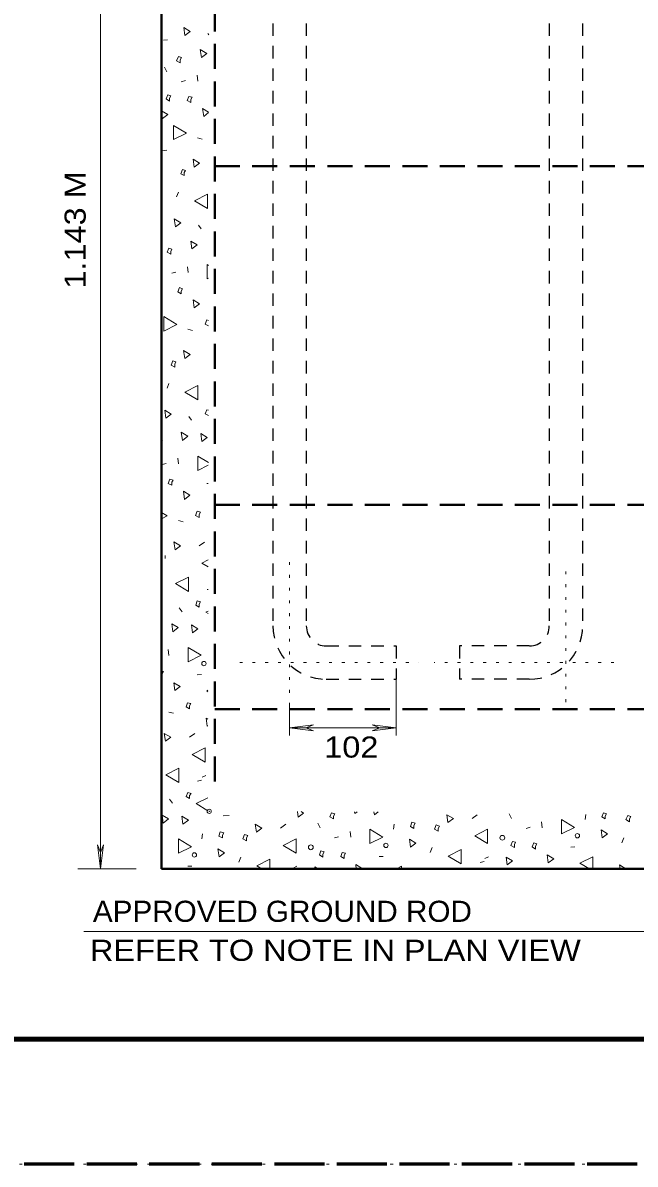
# Model space of a CAD drawing. Extents: x 312583 to 312854, y 144419 to 144597.
# Drawn here: x 312692.4 to 312714.43, y 144418.58 to 144459.67 of the extents above; entities that cross this region are included whole.
import ezdxf

# ---------------------------------------------------------------- set-up
doc = ezdxf.new("R2010")
doc.units = 0
doc.header["$LTSCALE"] = 0.3
doc.header["$PDMODE"] = 32
doc.header["$PDSIZE"] = 0.15
for name, pattern in [('DOTTED', [1.5, 0.3, -1.2]), ('LONG_DASHED', [7.5, 6, -1.5]), ('MEDIUM_DASHED', [4.5, 3, -1.5]), ('SHORT_DASHED', [2.7, 1.5, -1.2])]:
    doc.linetypes.add(name, pattern=pattern)
doc.layers.add('1', color=7, linetype='Continuous', lineweight=13)
doc.layers.add('63', color=7, linetype='DOTTED', lineweight=13)

msp = doc.modelspace()

# ---------------------------------------------------------------- linework, layer by layer
at = {"layer": '1'}
for p, q in [((312695.1883, 144429.2169), (312695.1883, 144472.3419)), ((312699.0599, 144459.2855), (312699.0906, 144459.2395)), ((312697.4576, 144459.0479), (312697.6033, 144459.0632)), ((312697.4959, 144458.0742), (312697.5803, 144457.9055)), ((312698.1016, 144457.5452), (312698.2473, 144457.5912)), ((312698.6689, 144457.7829), (312698.6919, 144457.5682)), ((312697.3886, 144456.4949), (312697.4269, 144456.2265)), ((312698.9066, 144456.3032), (312699.0829, 144456.4412)), ((312698.6843, 144455.5289), (312698.8529, 144455.4905)), ((312697.3886, 144455.0689), (312697.5803, 144455.0842)), ((312698.0019, 144453.5815), (312697.9253, 144453.4129)), ((312698.7149, 144452.3932), (312698.8146, 144452.2552)), ((312697.7566, 144450.6605), (312697.9023, 144450.6989)), ((312698.3239, 144450.8905), (312698.3469, 144450.6835)), ((312699.0829, 144450.9365), (312699.0293, 144450.9672)), ((312698.3393, 144448.6442), (312698.5079, 144448.5982)), ((312697.6569, 144446.6892), (312697.5879, 144446.5205)), ((312698.3699, 144445.5009), (312698.4696, 144445.3629)), ((312697.9789, 144443.9982), (312698.0019, 144443.7912)), ((312699.0753, 144443.8449), (312698.6919, 144444.0749)), ((312697.4116, 144443.7682), (312697.5573, 144443.8065)), ((312699.0216, 144443.0935), (312699.0676, 144443.0935)), ((312697.9943, 144441.7519), (312698.1629, 144441.7059)), ((312698.9296, 144440.9775), (312698.7456, 144440.8472)), ((312697.5189, 144440.3872), (312697.5189, 144440.4945)), ((312699.0293, 144439.2679), (312699.0676, 144439.2755)), ((312698.0249, 144438.6162), (312698.1323, 144438.4705)), ((312697.6339, 144437.1135), (312697.6569, 144436.8989)), ((312698.6766, 144436.2012), (312698.8223, 144436.2089)), ((312705.8296, 144436.0402), (312705.8296, 144434.0162)), ((312701.9963, 144435.0972), (312701.9963, 144434.0162)), ((312697.6493, 144434.8595), (312697.8179, 144434.8212)), ((312699.0369, 144434.3535), (312699.0599, 144434.3689)), ((312701.9963, 144434.2922), (312702.8626, 144434.3995)), ((312701.9963, 144434.2922), (312705.8296, 144434.2922)), ((312701.9963, 144434.2922), (312702.8626, 144434.1849)), ((312702.8626, 144434.3995), (312702.5866, 144434.2922)), ((312702.8626, 144434.1849), (312702.5866, 144434.2922)), ((312704.9633, 144434.3995), (312705.2393, 144434.2922)), ((312705.8296, 144434.2922), (312704.9633, 144434.3995)), ((312704.9633, 144434.1849), (312705.2393, 144434.2922)), ((312705.8296, 144434.2922), (312704.9633, 144434.1849)), ((312698.5846, 144434.0852), (312698.4006, 144433.9549)), ((312698.8529, 144432.5135), (312698.9833, 144432.5825)), ((312698.6843, 144432.3755), (312698.8299, 144432.4062)), ((312697.6799, 144431.7239), (312697.7873, 144431.5782)), ((312699.0983, 144431.2869), (312699.1059, 144431.2869)), ((312702.2799, 144431.2792), (312702.3106, 144431.0799)), ((312704.3346, 144431.2715), (312704.3423, 144431.2102)), ((312704.3423, 144431.2102), (312704.4266, 144431.2715)), ((312705.0323, 144431.2715), (312705.0476, 144431.1642)), ((312705.0476, 144431.1642), (312705.1856, 144431.2715)), ((312699.6043, 144431.1259), (312699.8189, 144431.1335)), ((312703.0083, 144430.8575), (312703.1003, 144430.6889)), ((312708.7506, 144431.1565), (312708.5666, 144431.0262)), ((312709.9006, 144431.2025), (312709.9849, 144431.0339)), ((312711.0659, 144430.9112), (312711.0889, 144430.6965)), ((312712.6299, 144430.9879), (312712.6529, 144431.1719)), ((312698.8453, 144430.2979), (312698.8683, 144430.4819)), ((312701.8583, 144430.8192), (312701.6743, 144430.6812)), ((312704.1813, 144430.5662), (312704.2043, 144430.3515)), ((312705.7376, 144430.6429), (312705.7606, 144430.8269)), ((312710.5063, 144430.6735), (312710.6519, 144430.7195)), ((312695.0809, 144430.0832), (312695.1883, 144429.8072)), ((312695.1883, 144429.2169), (312695.0809, 144430.0832)), ((312695.2956, 144430.0832), (312695.1883, 144429.8072)), ((312695.1883, 144429.2169), (312695.2956, 144430.0832)), ((312703.6139, 144430.3285), (312703.7596, 144430.3745)), ((312714.0253, 144430.3285), (312713.9486, 144430.1522)), ((312700.2483, 144429.6385), (312700.1716, 144429.4622)), ((312705.2239, 144429.6615), (312705.3696, 144429.6615)), ((312707.1329, 144429.9835), (312707.0563, 144429.8072)), ((312709.0189, 144429.5849), (312709.1493, 144429.6539)), ((312712.1163, 144429.9989), (312712.2619, 144430.0065)), ((312696.4763, 144429.2169), (312694.3756, 144429.2169)), ((312698.3316, 144429.3165), (312698.4773, 144429.3165)), ((312702.1266, 144429.2399), (312702.2569, 144429.3089)), ((312708.8503, 144429.4469), (312708.9959, 144429.4775)), ((312694.5903, 144426.9629), (312718.4949, 144426.9629))]:
    msp.add_line(p, q, dxfattribs=at)
at = {"layer": '1', "linetype": 'SHORT_DASHED', "lineweight": 25}
for p, q in [((312701.3983, 144470.1799), (312701.3983, 144437.9569)), ((312702.5943, 144470.1799), (312702.5943, 144437.9569)), ((312711.3419, 144470.1799), (312711.3419, 144437.9569)), ((312712.5379, 144470.1799), (312712.5379, 144437.9569)), ((312703.3149, 144437.2439), (312705.8296, 144437.2439)), ((312705.8296, 144437.2439), (312705.8296, 144436.0402)), ((312708.1066, 144437.2439), (312708.1066, 144436.0402)), ((312710.6213, 144437.2439), (312708.1066, 144437.2439)), ((312703.3149, 144436.0402), (312705.8296, 144436.0402)), ((312710.6213, 144436.0402), (312708.1066, 144436.0402))]:
    msp.add_line(p, q, dxfattribs=at)
at = {"layer": '1', "lineweight": 40}
for p, q in [((312697.3886, 144469.7122), (312697.3886, 144429.2169)), ((312697.3886, 144429.2169), (312740.7513, 144429.2169))]:
    msp.add_line(p, q, dxfattribs=at)
at = {"layer": '1', "linetype": 'MEDIUM_DASHED', "lineweight": 40}
for p, q in [((312699.3053, 144469.7122), (312699.3053, 144432.0919)), ((312699.3053, 144454.5092), (312738.8346, 144454.5092)), ((312699.3053, 144442.3192), (312738.8346, 144442.3192)), ((312699.3053, 144434.9669), (312738.8346, 144434.9669))]:
    msp.add_line(p, q, dxfattribs=at)
at = {"layer": '1', "linetype": 'DOTTED'}
for p, q in [((312701.9963, 144435.0972), (312701.9963, 144440.2645)), ((312711.9399, 144435.2199), (312711.9399, 144440.2645)), ((312700.2023, 144436.6459), (312706.6423, 144436.6459)), ((312713.6649, 144436.6459), (312707.1943, 144436.6459))]:
    msp.add_line(p, q, dxfattribs=at)
at = {"layer": '1', "lineweight": 158}
msp.add_line((312616.5, 144423.0846), (312849, 144423.0846), dxfattribs=at)
at = {"layer": '1', "linetype": 'LONG_DASHED', "lineweight": 60}
msp.add_line((312851.75, 144418.5846), (312583.526, 144418.5846), dxfattribs=at)
at = {"layer": '1'}
for points in [[(312698.2319, 144459.2165), (312698.4236, 144459.3622), (312698.1936, 144459.5079)], [(312698.0633, 144458.3349), (312698.1093, 144458.4192), (312697.9943, 144458.4575), (312697.9329, 144458.3042), (312698.0633, 144458.2275)], [(312698.8299, 144458.4269), (312699.0216, 144458.5725), (312698.7839, 144458.7105)], [(312697.6799, 144456.9625), (312697.7259, 144457.0469), (312697.6109, 144457.0775), (312697.5573, 144456.9319), (312697.6799, 144456.8552)], [(312698.4466, 144456.9089), (312698.4926, 144456.9932), (312698.3776, 144457.0239), (312698.3163, 144456.8782), (312698.4466, 144456.8015)], [(312697.8179, 144455.9812), (312697.8179, 144455.4675), (312698.2856, 144455.7052)], [(312698.5616, 144454.4785), (312698.7609, 144454.6242), (312698.5233, 144454.7622)], [(312698.2089, 144454.2792), (312698.2549, 144454.3559), (312698.1399, 144454.3942), (312698.0786, 144454.2409), (312698.2089, 144454.1719)], [(312699.0446, 144452.9912), (312699.0446, 144453.5049), (312698.5769, 144453.2672)], [(312697.8869, 144452.3319), (312698.0786, 144452.4775), (312697.8486, 144452.6155)], [(312698.4849, 144451.5345), (312698.6766, 144451.6802), (312698.4466, 144451.8182)], [(312697.7183, 144451.4425), (312697.7643, 144451.5269), (312697.6493, 144451.5652), (312697.5879, 144451.4119), (312697.7183, 144451.3429)], [(312698.1016, 144450.0165), (312698.1476, 144450.1009), (312698.0326, 144450.1392), (312697.9789, 144449.9859), (312698.1016, 144449.9169)], [(312698.5616, 144449.4109), (312698.7533, 144449.5565), (312698.5233, 144449.7022)], [(312697.4729, 144449.0965), (312697.4729, 144448.5752), (312697.9406, 144448.8129)], [(312698.2243, 144447.5862), (312698.4159, 144447.7319), (312698.1783, 144447.8775)], [(312697.8639, 144447.3869), (312697.9099, 144447.4635), (312697.7949, 144447.5019), (312697.7336, 144447.3485), (312697.8639, 144447.2795)], [(312698.6996, 144446.0989), (312698.6996, 144446.6125), (312698.2319, 144446.3825)], [(312697.5419, 144445.4395), (312697.7336, 144445.5852), (312697.5036, 144445.7232)], [(312698.1399, 144444.6422), (312698.3316, 144444.7879), (312698.1016, 144444.9335)], [(312698.8453, 144444.6039), (312699.0369, 144444.7495), (312698.8069, 144444.8875)], [(312697.7566, 144443.1319), (312697.8026, 144443.2085), (312697.6876, 144443.2469), (312697.6339, 144443.0935), (312697.7566, 144443.0245)], [(312698.2166, 144442.5185), (312698.4083, 144442.6719), (312698.1783, 144442.8099)], [(312698.7379, 144441.9742), (312698.7916, 144442.0509), (312698.6689, 144442.0892), (312698.6153, 144441.9359), (312698.7379, 144441.8669)], [(312697.8793, 144440.7015), (312698.0709, 144440.8472), (312697.8333, 144440.9852)], [(312698.3546, 144439.2065), (312698.3546, 144439.7202), (312697.8869, 144439.4902)], [(312698.7456, 144438.7389), (312698.7916, 144438.8232), (312698.6766, 144438.8615), (312698.6229, 144438.7082), (312698.7456, 144438.6392)], [(312697.7949, 144437.7499), (312697.9866, 144437.9032), (312697.7566, 144438.0412)], [(312698.5003, 144437.7115), (312698.6919, 144437.8572), (312698.4619, 144437.9952)], [(312698.3469, 144437.1902), (312698.3469, 144436.6689), (312698.8146, 144436.9065)], [(312697.8716, 144435.6339), (312698.0633, 144435.7795), (312697.8333, 144435.9175)], [(312698.4006, 144435.0819), (312698.4466, 144435.1662), (312698.3239, 144435.1969), (312698.2703, 144435.0435), (312698.4006, 144434.9745)], [(312697.5343, 144433.8092), (312697.7259, 144433.9549), (312697.4883, 144434.0929)], [(312698.9603, 144433.0579), (312698.9603, 144433.5715), (312698.4926, 144433.3339)], [(312698.0096, 144432.3219), (312698.0096, 144432.8355), (312697.5419, 144432.5979)], [(312698.4006, 144431.8542), (312698.4543, 144431.9309), (312698.3316, 144431.9692), (312698.2779, 144431.8159), (312698.4006, 144431.7469)], [(312697.4499, 144430.8652), (312697.6416, 144431.0109), (312697.4116, 144431.1489)], [(312698.1553, 144430.8192), (312698.3546, 144430.9649), (312698.1169, 144431.1105)], [(312703.5756, 144431.1182), (312703.6216, 144431.2025), (312703.5066, 144431.2332), (312703.4453, 144431.0875), (312703.5756, 144431.0109)], [(312706.4659, 144430.7732), (312706.5119, 144430.8575), (312706.3969, 144430.8959), (312706.3433, 144430.7425), (312706.4659, 144430.6659)], [(312707.6926, 144430.8805), (312707.8919, 144431.0262), (312707.6543, 144431.1642)], [(312711.7789, 144430.9879), (312711.7789, 144430.4742), (312712.2466, 144430.7042)], [(312713.3583, 144431.1182), (312713.4043, 144431.2025), (312713.2893, 144431.2332), (312713.2279, 144431.0875), (312713.3583, 144431.0109)], [(312714.2323, 144431.0185), (312714.2783, 144431.1029), (312714.1633, 144431.1335), (312714.1019, 144430.9879), (312714.2323, 144430.9112)], [(312699.5813, 144430.4282), (312699.6273, 144430.5125), (312699.5046, 144430.5509), (312699.4509, 144430.3975), (312699.5813, 144430.3285)], [(312700.4476, 144430.3285), (312700.4936, 144430.4129), (312700.3786, 144430.4512), (312700.3173, 144430.2979), (312700.4476, 144430.2289)], [(312700.8079, 144430.5355), (312700.9996, 144430.6812), (312700.7619, 144430.8192)], [(312704.8866, 144430.6429), (312704.8866, 144430.1292), (312705.3543, 144430.3592)], [(312707.3399, 144430.6735), (312707.3859, 144430.7579), (312707.2709, 144430.7962), (312707.2096, 144430.6429), (312707.3399, 144430.5739)], [(312709.1186, 144430.1292), (312709.1186, 144430.6429), (312708.6586, 144430.4052)], [(312713.2433, 144430.3362), (312713.4349, 144430.4819), (312713.2049, 144430.6199)], [(312698.0019, 144430.2979), (312698.0019, 144429.7842), (312698.4696, 144430.0142)], [(312702.2339, 144429.7842), (312702.2339, 144430.2979), (312701.7663, 144430.0602)], [(312706.3509, 144429.9912), (312706.5426, 144430.1369), (312706.3126, 144430.2825)], [(312710.0846, 144430.0909), (312710.1306, 144430.1752), (312710.0156, 144430.2059), (312709.9543, 144430.0525), (312710.0846, 144429.9835)], [(312710.8513, 144430.0372), (312710.8973, 144430.1215), (312710.7823, 144430.1522), (312710.7209, 144430.0065), (312710.8513, 144429.9299)], [(312699.4586, 144429.6462), (312699.6579, 144429.7919), (312699.4203, 144429.9375)], [(312703.1923, 144429.7459), (312703.2383, 144429.8302), (312703.1233, 144429.8609), (312703.0696, 144429.7152), (312703.1923, 144429.6385)], [(312703.9589, 144429.6922), (312704.0049, 144429.7765), (312703.8899, 144429.8072), (312703.8363, 144429.6615), (312703.9589, 144429.5849)], [(312708.1756, 144429.3932), (312708.1756, 144429.9069), (312707.7079, 144429.6692)], [(312709.8316, 144429.3549), (312710.0233, 144429.5005), (312709.7856, 144429.6385)], [(312711.3036, 144429.4315), (312711.5029, 144429.5772), (312711.2653, 144429.7152)]]:
    msp.add_lwpolyline(points, close=True, dxfattribs=at)
for points in [[(312697.4269, 144456.2265), (312697.6186, 144456.3722), (312697.3886, 144456.5102)], [(312699.0829, 144456.4565), (312698.8606, 144456.5869), (312698.9066, 144456.3032)], [(312697.3886, 144453.7195), (312697.4116, 144453.7349), (312697.3886, 144453.7579)], [(312699.0293, 144450.9672), (312699.0293, 144450.4535), (312699.0753, 144450.4765)], [(312699.0753, 144448.9585), (312699.0139, 144448.9815), (312698.9603, 144448.8282), (312699.0753, 144448.7592)], [(312699.0753, 144445.7309), (312699.0216, 144445.7462), (312698.9603, 144445.6005), (312699.0753, 144445.5392)], [(312697.3886, 144444.5809), (312697.4193, 144444.6345), (312697.3886, 144444.6499)], [(312698.6919, 144444.0749), (312698.6919, 144443.5612), (312699.0676, 144443.7529)], [(312697.3886, 144441.8209), (312697.5956, 144441.9205), (312697.3886, 144442.0432)], [(312699.0676, 144440.3412), (312698.8376, 144440.2262), (312699.0676, 144440.0882)], [(312697.3886, 144438.6929), (312697.3963, 144438.6929), (312697.3886, 144438.7005)], [(312699.0676, 144438.4935), (312698.9833, 144438.4552), (312699.0676, 144438.4092)], [(312697.4116, 144436.2395), (312697.4653, 144436.3239), (312697.3886, 144436.3469)], [(312697.3886, 144436.1475), (312697.4116, 144436.1322), (312697.4116, 144436.2395)], [(312699.0599, 144435.6492), (312699.0139, 144435.6185), (312699.0599, 144435.5879)], [(312699.0599, 144434.5989), (312698.9909, 144434.6372), (312699.0369, 144434.3535)], [(312699.0599, 144431.7775), (312698.6383, 144431.5629), (312699.0599, 144431.3099)], [(312702.3106, 144431.0799), (312702.5023, 144431.2255), (312702.4179, 144431.2792)], [(312712.9136, 144429.2169), (312712.9136, 144429.6539), (312712.4459, 144429.4162), (312712.7833, 144429.2169)], [(312701.2833, 144429.2169), (312701.2833, 144429.5619), (312700.8156, 144429.3242), (312700.9996, 144429.2169)], [(312703.0236, 144429.2169), (312702.9009, 144429.2935), (312702.9086, 144429.2169)], [(312704.5953, 144429.2169), (312704.6106, 144429.2322), (312704.3806, 144429.3702), (312704.3959, 144429.2169)], [(312706.0289, 144429.2169), (312706.0289, 144429.3089), (312705.8449, 144429.2169)], [(312714.1019, 144429.2169), (312713.8719, 144429.3625), (312713.8873, 144429.2169)]]:
    msp.add_lwpolyline(points, dxfattribs=at)
for centre, radius in [((312698.917, 144436.6081), 0.0784), ((312712.3534, 144430.4063), 0.0784), ((312702.7629, 144429.9919), 0.0865), ((312705.4631, 144430.0621), 0.0784), ((312709.6532, 144430.3362), 0.0865), ((312698.5728, 144429.7179), 0.0784)]:
    msp.add_circle(centre, radius, dxfattribs=at)
at = {"layer": '1', "linetype": 'SHORT_DASHED', "lineweight": 25}
for centre, radius, start, end in [((312703.3159, 144437.9607), 1.9167, 180, 270), ((312703.3159, 144437.9607), 0.7188, 180, 270), ((312710.6241, 144437.9607), 1.9167, 270, 0), ((312710.6241, 144437.9607), 0.7188, 270, 0)]:
    msp.add_arc(centre, radius, start, end, dxfattribs=at)
at = {"layer": '1'}
msp.add_point((312699.1059, 144431.2869), dxfattribs=at)
at = {"layer": '63'}
msp.add_lwpolyline([(312601.2, 144418.5846), (312853.5, 144418.5846), (312853.5, 144596.7846)], dxfattribs=at)

# ---------------------------------------------------------------- texts
at = {"layer": '1', "width": 1.15}
msp.add_text('1.143 M', height=0.76, rotation=90, dxfattribs=at).set_placement((312694.6607, 144450.104))
at = {"layer": '1'}
for s, width, p in [('102 ', 1.15, (312703.243, 144433.2209)), ('APPROVED GROUND ROD', 1.05, (312694.9197, 144427.308)), ('REFER TO NOTE IN PLAN VIEW', 1.15, (312694.8123, 144425.9042))]:
    msp.add_text(s, height=0.76, dxfattribs=dict(at, width=width)).set_placement(p)

doc.saveas('drawing.dxf')
